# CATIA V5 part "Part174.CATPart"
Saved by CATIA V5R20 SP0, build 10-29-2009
Part number: IA 6717SF
Revision: ANY
Definition: UNKNOWN
Nomenclature: IA 6717SF
Source: Unknown
Bounding box of the stored display mesh (mm): x -3.35 to 3.35, y -7.95 to 9.02, z -3.186 to 3.186
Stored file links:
  C:\Users\Utente\Desktop\IO LAVORO\3D X SITO CF\CUMSA\3D files FA\FA 126708-20\Part174.CATPart
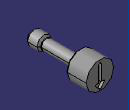
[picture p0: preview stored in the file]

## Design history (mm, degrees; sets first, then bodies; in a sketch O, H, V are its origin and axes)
Body1 "Cortar-Extruir2" (main body)
  Solid1: solid without history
